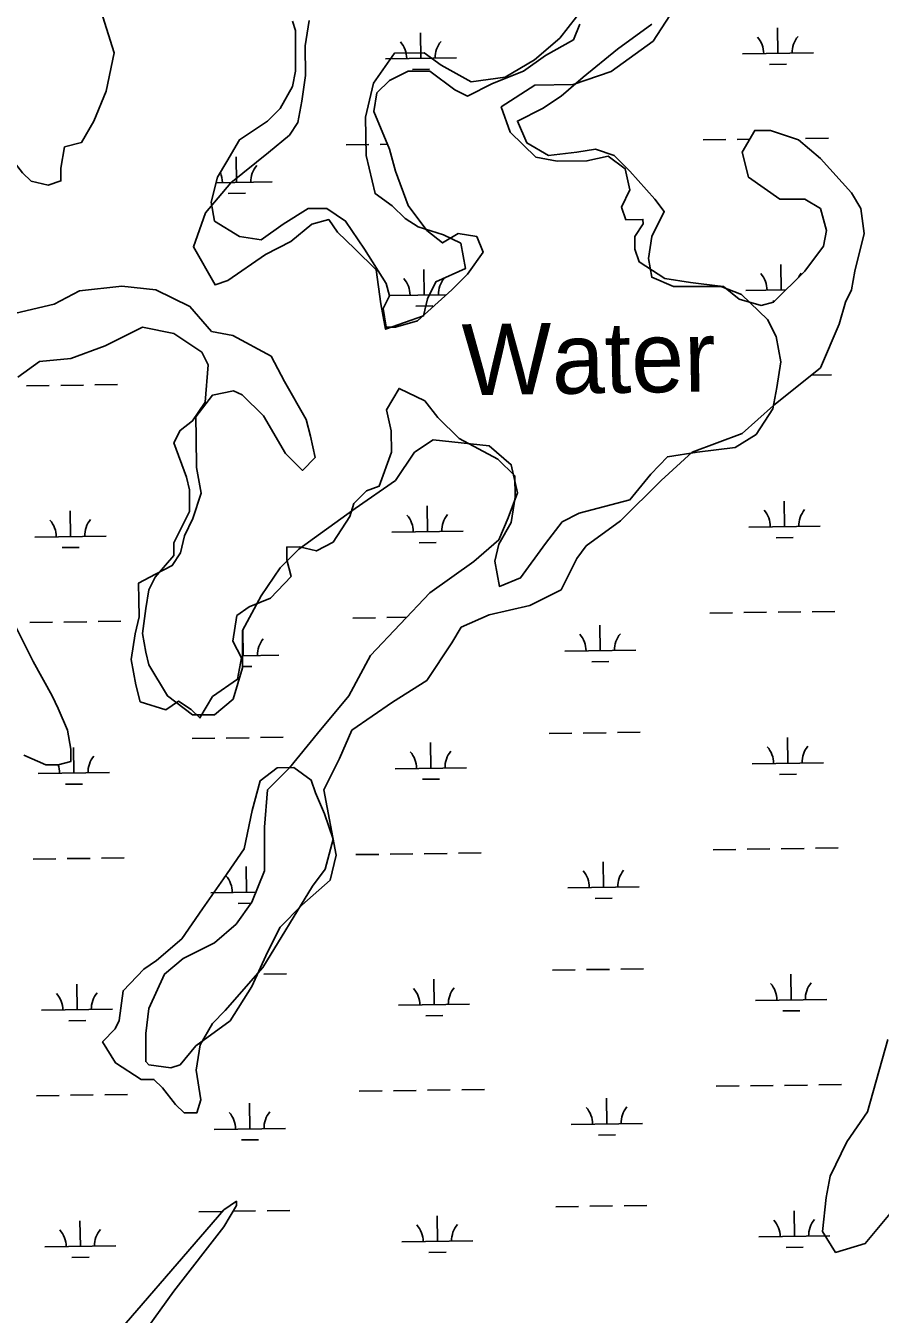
# Model space of a CAD drawing. Extents: x 3767014 to 3805179, y 361544 to 387384.
# Drawn here: x 3776248 to 3777449, y 377145 to 378956 of the extents above; entities that cross this region are included whole.
import ezdxf

# ---------------------------------------------------------------- set-up
doc = ezdxf.new("R2010")
doc.units = 0
for name, color, linetype in [('V-RIVR-IDEN', 7, 'Continuous'), ('V-TOPO-SHOR', 7, 'Continuous'), ('V-WETL-SWMP', 7, 'Continuous')]:
    doc.layers.add(name, color=color, linetype=linetype)

msp = doc.modelspace()

# ---------------------------------------------------------------- linework, layer by layer
at = {"layer": 'V-TOPO-SHOR'}
for points in [[(3776353.587, 378977.786), (3776372.313, 378918.377), (3776361.127, 378864.518), (3776343.81, 378822.509), (3776326.327, 378792.431), (3776302.546, 378786.134), (3776296.995, 378756.222), (3776297.244, 378738.324), (3776279.429, 378732.11), (3776255.483, 378737.744)], [(3775924.047, 378971.82), (3775942.193, 378954.171), (3775978.154, 378942.736), (3776014.115, 378931.302), (3776050.158, 378913.902), (3776056.87, 378860.292), (3776063.084, 378842.477), (3776111.225, 378813.311), (3776159.201, 378796.077), (3776201.21, 378778.759), (3776225.156, 378773.125), (3776243.385, 378749.51), (3776255.483, 378737.744)], [(3776234.188, 378552.472), (3776287.715, 378565.149), (3776323.262, 378583.544), (3776382.837, 378590.339), (3776430.647, 378585.036), (3776478.705, 378561.835), (3776509.031, 378526.455), (3776538.943, 378520.903), (3776593.05, 378491.82), (3776611.445, 378456.274), (3776642.02, 378402.996), (3776648.317, 378379.215), (3776654.697, 378349.469), (3776637.048, 378331.323), (3776612.854, 378354.855), (3776582.279, 378408.133), (3776552.035, 378437.547), (3776540.021, 378443.348), (3776510.274, 378436.967), (3776486.825, 378406.807), (3776487.24, 378376.978), (3776487.82, 378335.217), (3776494.283, 378299.505), (3776482.848, 378263.544), (3776471.248, 378239.515), (3776465.614, 378215.569), (3776453.931, 378197.505), (3776430.233, 378185.242), (3776406.536, 378172.979), (3776406.867, 378149.116), (3776407.199, 378125.252), (3776401.564, 378101.306), (3776396.096, 378065.428), (3776402.559, 378029.716), (3776408.856, 378005.936), (3776444.817, 377994.501), (3776462.549, 378006.682), (3776480.612, 377994.998), (3776492.709, 377983.233), (3776510.192, 378013.31), (3776545.656, 378037.671), (3776551.207, 378067.583), (3776538.944, 378091.281), (3776544.413, 378127.158), (3776562.145, 378139.339), (3776591.808, 378151.685), (3776621.223, 378181.928), (3776614.925, 378205.709), (3776614.677, 378223.606), (3776632.574, 378223.855), (3776656.521, 378218.22), (3776680.218, 378230.484), (3776703.584, 378266.61), (3776709.301, 378284.59), (3776726.95, 378302.737), (3776744.765, 378308.951), (3776761.999, 378356.926), (3776761.585, 378386.756), (3776755.205, 378416.502), (3776772.688, 378446.58), (3776808.732, 378429.179), (3776826.961, 378405.565), (3776857.204, 378376.15), (3776911.311, 378347.066), (3776935.506, 378323.535), (3776935.92, 378293.705), (3776930.452, 378257.828), (3776912.968, 378227.75), (3776907.334, 378203.804), (3776913.797, 378168.091), (3776943.461, 378180.438), (3776978.593, 378228.661), (3777002.042, 378258.822), (3777025.739, 378271.085), (3777097.081, 378289.977), (3777126.413, 378326.187), (3777149.944, 378350.381), (3777191.622, 378356.927), (3777245.232, 378363.639), (3777274.812, 378381.951), (3777298.179, 378418.077), (3777303.73, 378447.989), (3777309.199, 378483.867), (3777302.736, 378519.579), (3777290.472, 378543.277), (3777254.18, 378578.575), (3777224.185, 378590.092), (3777182.342, 378595.478), (3777146.464, 378600.946), (3777110.337, 378624.312), (3777104.123, 378642.127), (3777103.874, 378660.025), (3777115.557, 378678.088), (3777115.474, 378684.054), (3777091.611, 378683.722), (3777085.397, 378701.537), (3777096.997, 378725.566), (3777090.617, 378755.312), (3777066.505, 378772.878), (3777036.758, 378766.498), (3776994.997, 378765.918), (3776965.085, 378771.469), (3776928.793, 378806.767), (3776916.364, 378842.396), (3776963.677, 378872.889), (3777017.369, 378873.634), (3777070.813, 378892.278), (3777129.891, 378934.867), (3777153.257, 378970.994)], [(3777022.009, 378969.171), (3776998.56, 378939.01), (3776963.179, 378908.684), (3776921.75, 378884.24), (3776874.106, 378877.611), (3776832.014, 378900.894), (3776807.902, 378918.461), (3776766.141, 378917.88), (3776736.892, 378875.705), (3776725.623, 378827.813), (3776726.369, 378774.12), (3776739.047, 378720.594), (3776763.159, 378703.028), (3776781.305, 378685.379), (3776799.368, 378673.696), (3776835.329, 378662.261), (3776859.358, 378650.661), (3776865.821, 378614.949), (3776824.309, 378596.471), (3776812.709, 378572.442), (3776807.074, 378548.496), (3776753.63, 378529.853), (3776747.167, 378565.565), (3776740.538, 378613.209), (3776710.295, 378642.623), (3776686.1, 378666.155), (3776673.92, 378683.887), (3776650.139, 378677.59), (3776620.642, 378653.312), (3776585.095, 378634.917), (3776531.9, 378598.376), (3776514.085, 378592.162), (3776483.51, 378645.44), (3776500.745, 378693.415), (3776535.96, 378735.673), (3776589.072, 378778.18), (3776618.57, 378802.458), (3776630.253, 378820.521), (3776635.804, 378850.433), (3776641.273, 378886.311), (3776640.693, 378928.072), (3776646.161, 378963.95)], [(3777459.672, 377531.24), (3777431.252, 377429.407), (3777402.003, 377387.231), (3777378.803, 377339.173), (3777373.251, 377309.261), (3777367.948, 377261.452), (3777386.26, 377231.871), (3777427.855, 377244.383), (3777463.07, 377286.641)], [(3776321.525, 376990.335), (3776456.17, 377177.182), (3776526.517, 377267.664), (3776544, 377297.742), (3776543.918, 377303.708), (3776526.186, 377291.527), (3776338.263, 377074.105)]]:
    msp.add_lwpolyline(points, dxfattribs=at)
msp.add_lwpolyline([(3776581.12, 377632.409), (3776651.136, 377746.754), (3776668.702, 377770.866), (3776680.053, 377812.792), (3776667.624, 377848.422), (3776655.278, 377878.085), (3776649.064, 377895.9), (3776624.952, 377913.466), (3776601.089, 377913.134), (3776577.474, 377894.905), (3776566.122, 377852.979), (3776554.937, 377799.12), (3776525.688, 377756.945), (3776496.439, 377714.77), (3776467.189, 377672.595), (3776431.809, 377642.268), (3776414.077, 377630.088), (3776384.662, 377599.845), (3776379.277, 377558.001), (3776373.476, 377545.986), (3776355.828, 377527.84), (3776355.828, 377527.84), (3776374.139, 377498.26), (3776410.266, 377474.894), (3776428.163, 377475.142), (3776440.261, 377463.376), (3776458.49, 377439.762), (3776470.587, 377427.996), (3776488.485, 377428.244), (3776494.202, 377446.225), (3776487.656, 377487.903), (3776493.125, 377523.781), (3776510.608, 377553.858), (3776528.257, 377572.004)], close=True, dxfattribs=at)
at = {"layer": 'V-WETL-SWMP'}
for p, q in [((3776803.412, 378910.555), (3776802.912, 378946.551)), ((3777305.272, 378917.526), (3777304.772, 378953.523)), ((3776753.417, 378909.86), (3776853.407, 378911.249)), ((3777255.277, 378916.832), (3777355.267, 378918.221)), ((3777293.488, 378901.93), (3777317.485, 378902.263)), ((3776791.628, 378894.959), (3776815.625, 378895.292)), ((3777200.106, 378795.983), (3777232.103, 378796.427)), ((3777248.102, 378796.65), (3777265.592, 378796.892)), ((3777344.092, 378797.983), (3777376.089, 378798.427)), ((3776698.246, 378789.011), (3776730.243, 378789.456)), ((3776746.241, 378789.678), (3776756.169, 378789.816)), ((3776544.374, 378736.127), (3776543.874, 378772.123)), ((3776515.627, 378735.728), (3776594.369, 378736.821)), ((3776532.589, 378720.531), (3776556.587, 378720.864)), ((3776808.033, 378577.912), (3776807.533, 378613.908)), ((3777309.893, 378584.883), (3777309.393, 378620.88)), ((3776758.838, 378577.228), (3776839.203, 378578.345)), ((3777259.898, 378584.189), (3777316.287, 378584.972)), ((3776796.248, 378562.316), (3776820.246, 378562.649)), ((3777298.108, 378569.287), (3777300.646, 378569.322)), ((3776249.003, 378450.064), (3776281, 378450.508)), ((3776296.999, 378450.73), (3776328.996, 378451.175)), ((3776344.994, 378451.397), (3776376.991, 378451.842)), ((3777352.313, 378465.39), (3777380.71, 378465.785)), ((3776477.198, 378287.044), (3776478.038, 378287.055)), ((3777314.514, 378252.24), (3777314.014, 378288.237)), ((3776310.795, 378238.298), (3776310.295, 378274.294)), ((3776812.654, 378245.269), (3776812.154, 378281.266)), ((3777264.519, 378251.546), (3777364.509, 378252.935)), ((3776260.8, 378237.603), (3776360.79, 378238.992)), ((3776762.659, 378244.575), (3776862.649, 378245.964)), ((3777302.729, 378236.644), (3777326.727, 378236.978)), ((3776299.01, 378222.701), (3776323.008, 378223.035)), ((3776800.87, 378229.673), (3776824.867, 378230.006)), ((3776707.488, 378123.726), (3776739.485, 378124.17)), ((3776755.484, 378124.392), (3776783.453, 378124.781)), ((3777209.348, 378130.697), (3777241.345, 378131.141)), ((3777257.343, 378131.364), (3777289.34, 378131.808)), ((3777305.339, 378132.03), (3777337.336, 378132.475)), ((3777353.334, 378132.697), (3777385.331, 378133.142)), ((3776253.624, 378117.421), (3776285.621, 378117.865)), ((3776301.62, 378118.088), (3776333.616, 378118.532)), ((3776349.615, 378118.754), (3776381.612, 378119.199)), ((3776553.616, 378070.841), (3776553.116, 378106.838)), ((3777055.476, 378077.813), (3777054.976, 378113.809)), ((3776552.674, 378070.828), (3776603.611, 378071.536)), ((3777005.48, 378077.118), (3777105.471, 378078.507)), ((3776552.674, 378055.396), (3776565.829, 378055.578)), ((3777043.691, 378062.216), (3777067.689, 378062.55)), ((3776983.678, 377961.372), (3777015.675, 377961.817)), ((3777031.673, 377962.039), (3777063.67, 377962.483)), ((3777079.669, 377962.706), (3777111.666, 377963.15)), ((3776315.416, 377905.655), (3776314.915, 377941.651)), ((3776481.818, 377954.401), (3776513.815, 377954.845)), ((3776529.814, 377955.067), (3776561.811, 377955.512)), ((3776577.809, 377955.734), (3776609.806, 377956.179)), ((3776817.275, 377912.626), (3776816.775, 377948.623)), ((3777319.135, 377919.598), (3777318.635, 377955.594)), ((3776265.42, 377904.96), (3776365.411, 377906.349)), ((3776767.28, 377911.932), (3776867.27, 377913.321)), ((3777269.139, 377918.903), (3777369.13, 377920.292)), ((3777307.35, 377904.001), (3777331.348, 377904.335)), ((3776303.631, 377890.058), (3776327.629, 377890.392)), ((3776805.491, 377897.03), (3776829.488, 377897.363)), ((3777213.969, 377798.054), (3777245.966, 377798.499)), ((3777261.964, 377798.721), (3777293.961, 377799.165)), ((3777309.959, 377799.388), (3777341.956, 377799.832)), ((3777357.955, 377800.054), (3777389.952, 377800.499)), ((3776258.245, 377784.778), (3776290.242, 377785.222)), ((3776306.24, 377785.445), (3776338.237, 377785.889)), ((3776354.236, 377786.111), (3776386.233, 377786.556)), ((3776712.109, 377791.083), (3776744.106, 377791.527)), ((3776760.105, 377791.749), (3776792.101, 377792.194)), ((3776808.1, 377792.416), (3776840.097, 377792.861)), ((3776856.095, 377793.083), (3776888.092, 377793.527)), ((3777060.096, 377745.17), (3777059.596, 377781.166)), ((3776558.237, 377738.198), (3776557.737, 377774.195)), ((3777010.101, 377744.475), (3777110.092, 377745.864)), ((3776508.242, 377737.504), (3776571.492, 377738.382)), ((3777048.312, 377729.574), (3777072.31, 377729.907)), ((3776546.452, 377722.602), (3776564.847, 377722.858)), ((3776582.43, 377623.091), (3776614.427, 377623.536)), ((3776821.896, 377579.983), (3776821.396, 377615.98)), ((3776988.299, 377628.729), (3777020.296, 377629.174)), ((3777036.294, 377629.396), (3777068.291, 377629.84)), ((3777084.29, 377630.063), (3777116.287, 377630.507)), ((3777323.755, 377586.955), (3777323.255, 377622.951)), ((3776320.036, 377573.012), (3776319.536, 377609.008)), ((3776771.901, 377579.289), (3776871.891, 377580.678)), ((3777273.76, 377586.26), (3777373.751, 377587.649)), ((3776270.041, 377572.317), (3776370.032, 377573.706)), ((3776810.111, 377564.387), (3776834.109, 377564.72)), ((3777311.971, 377571.358), (3777335.969, 377571.692)), ((3776308.252, 377557.416), (3776332.25, 377557.749)), ((3776262.866, 377452.135), (3776294.863, 377452.579)), ((3776310.861, 377452.802), (3776342.858, 377453.246)), ((3776358.857, 377453.468), (3776390.853, 377453.913)), ((3776716.73, 377458.44), (3776748.727, 377458.884)), ((3776764.725, 377459.106), (3776796.722, 377459.551)), ((3776812.721, 377459.773), (3776844.718, 377460.218)), ((3776860.716, 377460.44), (3776892.713, 377460.884)), ((3777218.59, 377465.411), (3777250.586, 377465.856)), ((3777266.585, 377466.078), (3777298.582, 377466.522)), ((3777314.58, 377466.745), (3777346.577, 377467.189)), ((3777362.576, 377467.411), (3777394.573, 377467.856)), ((3776562.858, 377405.555), (3776562.358, 377441.552)), ((3777064.717, 377412.527), (3777064.217, 377448.523)), ((3776512.863, 377404.861), (3776612.853, 377406.25)), ((3777014.722, 377411.832), (3777114.712, 377413.221)), ((3777052.933, 377396.931), (3777076.93, 377397.264)), ((3776551.073, 377389.959), (3776575.071, 377390.293)), ((3776491.06, 377289.115), (3776523.057, 377289.559)), ((3776539.056, 377289.782), (3776571.052, 377290.226)), ((3776587.051, 377290.448), (3776619.048, 377290.893)), ((3776992.92, 377296.086), (3777024.917, 377296.531)), ((3777040.915, 377296.753), (3777072.912, 377297.198)), ((3777088.91, 377297.42), (3777120.907, 377297.864)), ((3777328.376, 377254.312), (3777327.876, 377290.308)), ((3776324.657, 377240.369), (3776324.157, 377276.365)), ((3776826.517, 377247.34), (3776826.017, 377283.337)), ((3777278.381, 377253.617), (3777378.371, 377255.006)), ((3776274.662, 377239.674), (3776374.652, 377241.063)), ((3776776.522, 377246.646), (3776876.512, 377248.035)), ((3777316.592, 377238.716), (3777340.589, 377239.049)), ((3776312.873, 377224.773), (3776336.87, 377225.106)), ((3776814.732, 377231.744), (3776838.73, 377232.077))]:
    msp.add_line(p, q, dxfattribs=at)
for points in [[(3776816.095, 378159.162), (3776732.679, 378071.302), (3776701.946, 378014.193), (3776658.043, 377961.477), (3776618.53, 377913.155), (3776587.797, 377882.404), (3776583.407, 377829.688), (3776583.407, 377768.186), (3776565.845, 377724.256), (3776543.894, 377693.505), (3776513.161, 377667.147), (3776469.258, 377645.183), (3776442.916, 377623.218), (3776420.964, 377574.895), (3776416.573, 377539.751), (3776416.573, 377500.214), (3776420.964, 377495.821), (3776451.696, 377491.428), (3776464.867, 377495.821), (3776486.819, 377522.179), (3776535.113, 377557.323), (3776565.845, 377605.646), (3776587.797, 377653.969), (3776605.359, 377689.112), (3776636.091, 377719.863), (3776675.604, 377755.007), (3776684.385, 377790.151), (3776666.823, 377882.404), (3776688.775, 377926.334), (3776706.337, 377965.87), (3776763.411, 378005.407), (3776811.705, 378036.158), (3776846.828, 378088.874), (3776859.999, 378110.839), (3776899.512, 378128.411), (3776956.587, 378141.59), (3777000.49, 378163.555), (3777022.442, 378207.485), (3777035.613, 378225.057), (3777083.907, 378260.2), (3777140.981, 378317.309), (3777184.885, 378356.846), (3777255.13, 378383.204), (3777299.034, 378422.741), (3777364.889, 378475.457), (3777391.231, 378536.958), (3777400.012, 378567.709), (3777408.793, 378585.281), (3777413.183, 378611.639), (3777426.354, 378664.355), (3777421.964, 378699.499), (3777408.793, 378721.464), (3777364.889, 378769.787), (3777334.157, 378796.145), (3777294.644, 378809.324), (3777272.692, 378809.324), (3777255.13, 378778.573), (3777263.911, 378743.429), (3777307.815, 378712.678), (3777342.938, 378712.678), (3777364.889, 378699.499), (3777373.67, 378668.748), (3777369.28, 378646.783), (3777342.938, 378611.639), (3777299.034, 378567.709), (3777281.473, 378563.316), (3777250.74, 378572.102), (3777228.788, 378589.674), (3777158.543, 378589.674), (3777127.81, 378602.853), (3777123.42, 378629.211), (3777127.81, 378659.962), (3777145.372, 378695.106), (3777132.201, 378712.678), (3777097.078, 378752.215), (3777075.126, 378774.18), (3777048.784, 378782.966), (3777022.442, 378778.573), (3776982.929, 378774.18), (3776952.196, 378791.752), (3776939.025, 378822.503), (3776974.148, 378840.074), (3777000.49, 378857.646), (3777031.223, 378884.004), (3777079.516, 378923.541), (3777127.81, 378958.685)], [(3777026.832, 378958.685), (3777018.052, 378936.72), (3776978.538, 378914.755), (3776947.806, 378892.79), (3776903.902, 378875.218), (3776868.78, 378857.646), (3776851.218, 378866.432), (3776816.095, 378892.79), (3776785.363, 378892.79), (3776759.021, 378879.611), (3776741.459, 378862.039), (3776737.069, 378835.681), (3776759.021, 378782.966), (3776767.802, 378752.215), (3776785.363, 378703.892), (3776811.705, 378668.748), (3776833.657, 378651.176), (3776855.609, 378664.355), (3776881.951, 378659.962), (3776890.731, 378637.997), (3776868.78, 378607.246), (3776846.828, 378585.281), (3776798.534, 378541.351), (3776767.802, 378532.566), (3776754.63, 378532.566), (3776750.24, 378558.923), (3776759.021, 378576.495), (3776754.63, 378594.067), (3776723.898, 378642.39), (3776697.556, 378681.927), (3776671.214, 378699.499), (3776644.872, 378699.499), (3776609.749, 378677.534), (3776579.016, 378655.569), (3776548.284, 378659.962), (3776513.161, 378681.927), (3776508.771, 378708.285), (3776517.551, 378743.429), (3776530.723, 378765.394), (3776548.284, 378796.145), (3776587.797, 378822.503), (3776605.359, 378840.074), (3776622.92, 378870.825), (3776627.31, 378892.79), (3776627.31, 378949.899), (3776622.92, 378963.078)], [(3776236.569, 378462.278), (3776267.301, 378484.243), (3776311.205, 378488.636), (3776359.499, 378506.208), (3776412.183, 378532.566), (3776456.087, 378523.78), (3776495.6, 378497.422), (3776504.38, 378479.85), (3776499.99, 378427.134), (3776482.429, 378400.776), (3776464.867, 378387.597), (3776456.087, 378370.025), (3776473.648, 378321.702), (3776478.038, 378304.13), (3776478.038, 378273.379), (3776456.087, 378229.45), (3776456.087, 378211.878), (3776429.744, 378181.127), (3776420.964, 378163.555), (3776416.573, 378137.197), (3776412.183, 378102.053), (3776416.573, 378075.695), (3776420.964, 378058.123), (3776447.306, 378014.193), (3776482.429, 377987.835), (3776513.161, 377987.835), (3776539.503, 378009.8), (3776552.674, 378053.73), (3776552.674, 378106.446), (3776579.016, 378154.769), (3776605.359, 378194.306), (3776631.701, 378220.664), (3776662.433, 378242.628), (3776710.727, 378277.772), (3776767.802, 378317.309), (3776794.144, 378356.846), (3776820.486, 378374.418), (3776899.512, 378365.632), (3776930.245, 378339.274), (3776939.025, 378299.737), (3776925.854, 378264.593), (3776912.683, 378233.843), (3776877.56, 378203.092), (3776816.095, 378159.162)], [(3776245.35, 377930.727), (3776276.082, 377917.548), (3776293.644, 377917.548), (3776311.205, 377921.941), (3776311.205, 377939.513), (3776306.815, 377965.87), (3776293.644, 377996.621), (3776284.863, 378014.193), (3776258.521, 378062.516), (3776232.179, 378115.232)]]:
    msp.add_lwpolyline(points, dxfattribs=at)
for centre, start, end in [((3777250.028, 378917.234), 0.024037, 41.567695), ((3777360.503, 378918.768), 140.024034, 181.567693), ((3776748.168, 378910.262), 0.024037, 41.567696), ((3776858.643, 378911.797), 140.024034, 181.567693), ((3776599.605, 378737.369), 140.024034, 181.567693), ((3776489.13, 378735.834), 0.024037, 23.547548), ((3776752.789, 378577.619), 0.024037, 41.567696), ((3776863.264, 378579.154), 140.024034, 181.567693), ((3777254.649, 378584.591), 0.024037, 41.567695), ((3777365.124, 378586.125), 140.024034, 151.895323), ((3776757.41, 378244.976), 0.024037, 41.567695), ((3776867.885, 378246.511), 140.024034, 181.567693), ((3777259.27, 378251.948), 0.024037, 41.567695), ((3777369.745, 378253.483), 140.024034, 181.567693), ((3776255.55, 378238.005), 0.024037, 41.567695), ((3776366.026, 378239.54), 140.024034, 181.567693), ((3776608.847, 378072.083), 140.024034, 181.567693), ((3777000.231, 378077.52), 0.024037, 41.567695), ((3777110.707, 378079.055), 140.024034, 181.567693), ((3777263.89, 377919.305), 0.024037, 41.567695), ((3777374.366, 377920.84), 140.024034, 181.567693), ((3776370.647, 377906.897), 140.024034, 181.567693), ((3776762.031, 377912.334), 0.024037, 41.567695), ((3776872.506, 377913.868), 140.024034, 181.567693), ((3776260.171, 377905.362), 0.024037, 20.226786), ((3776502.993, 377737.906), 0.024037, 41.567695), ((3777004.852, 377744.877), 0.024037, 41.567695), ((3777115.327, 377746.412), 140.024034, 181.567693), ((3776375.267, 377574.254), 140.024034, 181.567693), ((3776766.652, 377579.691), 0.024037, 41.567695), ((3776877.127, 377581.225), 140.024034, 181.567693), ((3777268.511, 377586.662), 0.024037, 41.567695), ((3777378.986, 377588.197), 140.024034, 181.567693), ((3776264.792, 377572.719), 0.024037, 41.567695), ((3777009.473, 377412.234), 0.024037, 41.567695), ((3777119.948, 377413.769), 140.024034, 181.567693), ((3776507.614, 377405.263), 0.024037, 41.567695), ((3776618.089, 377406.797), 140.024034, 181.567693), ((3776771.273, 377247.048), 0.024037, 41.567695), ((3776881.748, 377248.582), 140.024034, 181.567693), ((3777273.132, 377254.019), 0.024037, 41.567695), ((3777383.607, 377255.554), 140.024034, 181.567693), ((3776269.413, 377240.076), 0.024037, 41.567695), ((3776379.888, 377241.611), 140.024034, 181.567693)]:
    msp.add_arc(centre, 35.246, start, end, dxfattribs=at)

# ---------------------------------------------------------------- texts
at = {"layer": 'V-RIVR-IDEN'}
msp.add_text('Water', height=100, rotation=0.919589, dxfattribs=at).set_placement((3776861.83, 378436.745))

doc.saveas('drawing.dxf')
